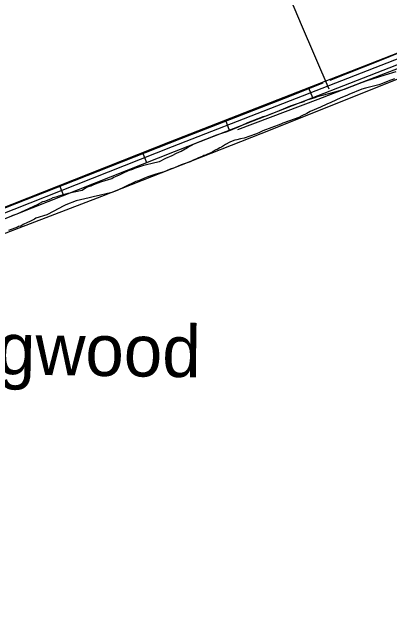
# Model space of a CAD drawing. Extents: x 3329297 to 3367176, y 649250 to 674653.
# Drawn here: x 3344410 to 3345468, y 668907 to 670634 of the extents above; entities that cross this region are included whole.
import ezdxf

# ---------------------------------------------------------------- set-up
doc = ezdxf.new("R2010")
doc.units = 0
for name, color, linetype in [('V-DTCH-CNTR', 7, 'Continuous'), ('V-ROAD-CNTR', 7, 'Continuous'), ('V-SITE-VEGE', 7, 'Continuous'), ('V-TOPO-GNAM-IDEN', 7, 'Continuous'), ('V-TOPO-SHOR', 7, 'Continuous')]:
    doc.layers.add(name, color=color, linetype=linetype)

msp = doc.modelspace()

# ---------------------------------------------------------------- linework, layer by layer
at = {"layer": 'V-DTCH-CNTR'}
for points in [[(3345298.1, 670418.5), (3345220.4, 670599.1), (3345151.3, 670763.2)], [(3344271.9, 669969), (3344661, 670118.3), (3345107.1, 670293.6), (3345498.4, 670450.2)]]:
    msp.add_lwpolyline(points, dxfattribs=at)
at = {"layer": 'V-ROAD-CNTR'}
for p, q in [((3345240.3, 670422.3), (3345251.2, 670394.4)), ((3345007.4, 670331.4), (3345018.3, 670303.5)), ((3344774.6, 670240.1), (3344785.6, 670212.3)), ((3344542.1, 670148.2), (3344553.1, 670120.3))]:
    msp.add_line(p, q, dxfattribs=at)
for points in [[(3341478.7, 668921.1), (3342192.1, 669201.3), (3342356.2, 669268.6), (3343000.4, 669522.2), (3344144.6, 669974.9), (3344859.3, 670257.5), (3345736.7, 670600), (3346977.7, 671089.4), (3347844, 671430), (3349239.5, 671977)], [(3341484.2, 668907.2), (3342197.7, 669187.4), (3342361.8, 669254.7), (3343005.9, 669508.3), (3344150.1, 669961), (3344864.8, 670243.5), (3345742.2, 670586), (3346478.7, 670876.5)], [(3343947.7, 669913.2), (3344139.1, 669988.9), (3344853.8, 670271.5), (3345622.3, 670571.4)]]:
    msp.add_lwpolyline(points, dxfattribs=at)
at = {"layer": 'V-SITE-VEGE'}
for points in [[(3344638.4, 670151), (3344658.4, 670158), (3344670, 670161.5), (3344688.4, 670167.7), (3344693, 670170.2), (3344710.6, 670177.9), (3344719.8, 670182.9), (3344735.9, 670189.8), (3344747.4, 670194.1), (3344753.6, 670196.7), (3344779, 670204.7), (3344809.1, 670212.1), (3344822.2, 670215.7), (3344840.5, 670224.2), (3344858.2, 670231.9), (3344870.4, 670238.6), (3344883.4, 670244.6), (3344900.9, 670254.6), (3344920, 670264.7), (3344926.1, 670267.3), (3344982.9, 670289.7), (3344997.5, 670295), (3345012.2, 670299.4), (3345044.4, 670312.4), (3345054.3, 670317.4), (3345070.4, 670325), (3345098.8, 670335.5), (3345108.8, 670339.8), (3345113.4, 670341.5), (3345124.2, 670344.3), (3345149.5, 670354.6), (3345158.7, 670358.8), (3345176.4, 670365.8), (3345190.2, 670371), (3345217.9, 670380.6), (3345227.9, 670383.3), (3345230.2, 670385), (3345237, 670388.4), (3345259.4, 670394.7), (3345268.6, 670398.2), (3345283.2, 670402.6), (3345307.9, 670409), (3345341.1, 670418.1), (3345384.1, 670434.6), (3345394.8, 670438.9), (3345401.7, 670441.5), (3345454.9, 670458.3), (3345486.4, 670468.1)], [(3345481.8, 670446.9), (3345463.3, 670440.7), (3345448, 670433.9), (3345437.2, 670430.4), (3345400.2, 670421.2), (3345389.4, 670418.4), (3345353.4, 670403), (3345348, 670400.4), (3345331.1, 670393.6), (3345302.8, 670380.8), (3345292.1, 670375.7), (3345273.7, 670368), (3345244.6, 670355.2), (3345235.4, 670350.1), (3345221.6, 670343.4), (3345213.2, 670339.1), (3345187.1, 670329.6), (3345168.7, 670322.6), (3345162.5, 670320), (3345112.6, 670301), (3345101.1, 670295.8), (3345092, 670291.6), (3345059.6, 670281), (3345049.6, 670279.1), (3345039.6, 670276.3), (3345034.1, 670275.3), (3345031.1, 670274.4), (3345019.6, 670269.3), (3345007.4, 670262.6), (3344996.7, 670255.2), (3344992.1, 670253.5), (3344984.5, 670249.3), (3344980.7, 670247.6), (3344972.3, 670243.3), (3344970, 670241.7), (3344966.2, 670239.2), (3344957, 670235.7), (3344951.6, 670233.2), (3344947, 670232.2), (3344943.2, 670229.7), (3344939.4, 670228), (3344931.7, 670225.4), (3344924.8, 670222), (3344917.1, 670218.6), (3344908.7, 670214.4), (3344894.9, 670210), (3344883.3, 670205.6), (3344864.9, 670197.9), (3344852.6, 670193.5), (3344835.8, 670186.6), (3344825, 670183.9), (3344811.9, 670179.5), (3344789.6, 670172.4), (3344780.3, 670168.9), (3344763.5, 670161.3), (3344756.6, 670159.4), (3344725.2, 670144.2), (3344703.8, 670134), (3344688.4, 670128.7), (3344656.8, 670120.5), (3344636.7, 670115.8), (3344625.1, 670113.1), (3344588.8, 670104.6), (3344559.6, 670093.4), (3344552.7, 670090), (3344526, 670075.7), (3344506.9, 670065.6)], [(3344409.6, 670063.4), (3344423.4, 670068.6), (3344445.6, 670078.9), (3344480.1, 670094.2), (3344495.4, 670102.6), (3344500.8, 670104.4), (3344517.7, 670110.5), (3344524.6, 670113.8), (3344535.3, 670117.4), (3344539.9, 670119.1), (3344566.1, 670126.4), (3344583.1, 670130.1), (3344605.6, 670134.9), (3344612.4, 670139.1), (3344617, 670142.3), (3344628.5, 670146.7), (3344630.8, 670146.8), (3344638.4, 670151)], [(3344506.9, 670065.6), (3344476.1, 670055.9), (3344471.6, 670053.4), (3344458.6, 670046.6), (3344452.4, 670044.1), (3344440.2, 670038.1), (3344433.4, 670034), (3344427.2, 670032.9), (3344424.1, 670031.3), (3344398.8, 670021.7)]]:
    msp.add_lwpolyline(points, dxfattribs=at)
at = {"layer": 'V-TOPO-SHOR'}
for points in [[(3345042.4, 670305), (3345267.5, 670390.1), (3345603.8, 670520), (3345822.1, 670602)], [(3345300.6, 670443.4), (3345444.8, 670500.7), (3345617.2, 670571)], [(3344148.5, 669989.1), (3344364.7, 670076.2), (3344584.2, 670161.9), (3344885.2, 670280.9), (3345187.8, 670398.5), (3345281, 670436.3)]]:
    msp.add_lwpolyline(points, dxfattribs=at)

# ---------------------------------------------------------------- texts
at = {"layer": 'V-TOPO-GNAM-IDEN'}
msp.add_text('Longwood', height=145, rotation=359.1629, dxfattribs=at).set_placement((3344042.4, 669622.7))

doc.saveas('drawing.dxf')
